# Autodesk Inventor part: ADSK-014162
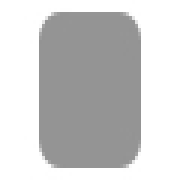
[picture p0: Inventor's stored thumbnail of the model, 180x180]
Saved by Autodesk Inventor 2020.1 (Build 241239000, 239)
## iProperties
Created: 2019-01
Part Number: ADSK-014162
Material: Stahl, weich
Document SubType Name: Modeling
Designer: lutzd
Language: de-DE
Size Designation: 5 x 39,384472 x 39,384472
Categories: <MemberInstance><Categories><Category DisplayName="Sonstige Bauteile" InternalName="5aa15e00-363f-49f2-933f-16f664388e3f" Mnemonic="OTHER"><Category DisplayName
Mass: 60.0398 g
Surface Area: 38.0412 cm^2
Volume: 7.64838 cm^3
Density: 7.85 g/cm^3
Appearance: Halbpoliert
IsCustomPart: 1
Title: end cap
Author: lutzd
Revision Number: -
Dimensions: 39,4x39,4x5 mm
Mass: 0,06 kg
DocNumber: ADSK-014162
Folder: 01 - Themengebiete\Simplification\01 - Packaging machine\
VDS_Category: 3D Komponenten
VDS_NumSchm: Autodesk
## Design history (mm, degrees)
sketch "Sketch1"
  geometry: L1 (0, 20.175)-(0, -21.446); L2 (-20.203, 0)-(20.169, 0); L3 (-19.692, 19.692)-(19.692, 19.692); L4 (19.692, 19.692)-(19.692, -19.692); L5 (19.692, -19.692)-(-19.692, -19.692); L6 (-19.692, -19.692)-(-19.692, 19.692); 1 further point
  constraints: 12 end point, 2 horizontal, 2 parallel, 2 point on line, 1 perpendicular, 1 vertical
  dimensions: "d0" = 39.38447 distance between parallel lines of L5 L3 (= height); "d1" = 19.69224 distance between parallel lines of L2 L3 (= 0.5 x height); "d2" = 39.38447 distance between parallel lines of L6 L4 (= width); "d3" = 19.69224 distance between parallel lines of L6 L1 (= 0.5 x width)
extrude "Extrusion1" new body sketch "Sketch1" distance "d4" = 5 (= thickness); taper "d5" = 0 deg
fillet "Fillet1" dims "d6" = 5 (= fillet), "d7" = 0, "fillet" = 5 [user parameter; used in 1 equation term]
chamfer "Chamfer1" distance "d8" = 0 (computed from chamfer); stored, may be unused: second distance "d9" = 2, angle "d10" = 45 deg; dims "d11" = 0, "chamfer" = 0 [user parameter; used in 1 equation term]
body "Solid1"
other parameters: "thickness" = 5 [user parameter; used in 1 equation term], "width" = 39.38447 [user parameter; used in 2 equation terms], "height" = 39.38447 [user parameter; used in 2 equation terms]
